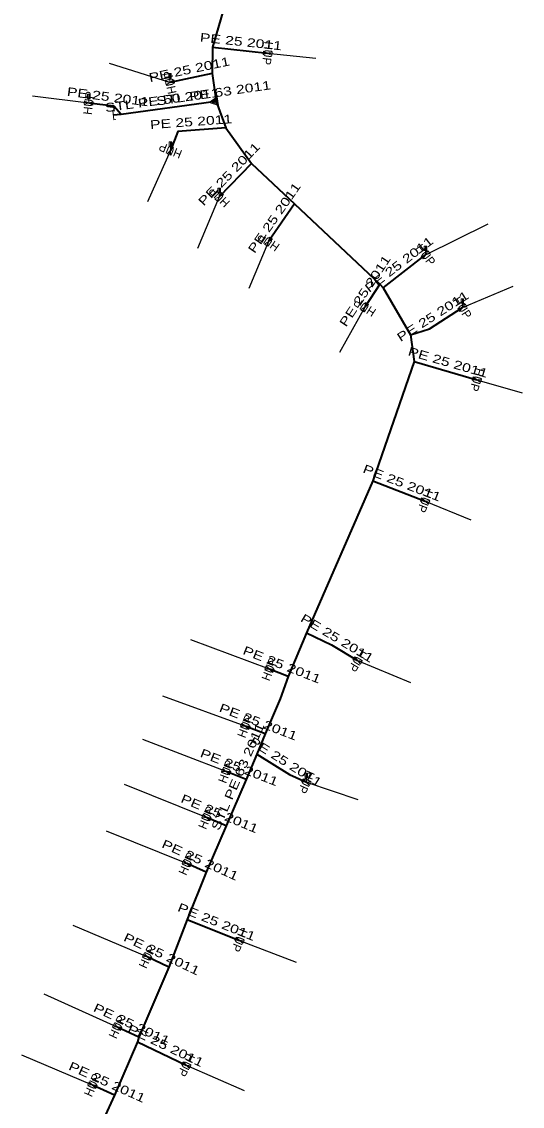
# Model space of a CAD drawing. Extents: x -737484 to -734496, y -1033882 to -1030666.
# Drawn here: x -735609.6 to -735552.2, y -1032516.8 to -1032392.5 of the extents above; entities that cross this region are included whole.
import ezdxf
from ezdxf.enums import TextEntityAlignment as Align

# ---------------------------------------------------------------- set-up
doc = ezdxf.new("R2010")
doc.units = 0
doc.header["$LTSCALE"] = 0.4
for name, color, linetype, lineweight in [('1', 7, 'Continuous', 13), ('22', 7, 'Continuous', 25), ('5', 7, 'Continuous', 35), ('7', 7, 'Continuous', 35)]:
    doc.layers.add(name, color=color, linetype=linetype, lineweight=lineweight)
doc.layers.add('2', color=7, linetype='Continuous')

msp = doc.modelspace()

# ---------------------------------------------------------------- linework, layer by layer
at = {"layer": '1'}
for p, q in [((-735592.6, -1032399.45), (-735592.6, -1032398.95)), ((-735592.525, -1032398.875), (-735592.525, -1032398.525)), ((-735601.914, -1032401.817), (-735601.914, -1032401.317)), ((-735601.839, -1032401.242), (-735601.839, -1032400.892)), ((-735592.55, -1032407.25), (-735592.55, -1032406.75)), ((-735592.475, -1032406.675), (-735592.475, -1032406.325)), ((-735586.875, -1032411.995), (-735586.875, -1032411.645)), ((-735586.95, -1032412.57), (-735586.95, -1032412.07)), ((-735563.29, -1032419.23), (-735563.29, -1032418.73)), ((-735563.215, -1032418.655), (-735563.215, -1032418.305)), ((-735558.995, -1032424.705), (-735558.995, -1032424.355)), ((-735559.07, -1032425.28), (-735559.07, -1032424.78)), ((-735576.885, -1032479.095), (-735576.885, -1032478.745)), ((-735576.96, -1032479.67), (-735576.96, -1032479.17))]:
    msp.add_line(p, q, dxfattribs=at)
for points in [[(-735580.881, -1032395.963), (-735580.923, -1032396.361), (-735581.876, -1032395.858), (-735581.918, -1032396.256)], [(-735593.047, -1032399.749), (-735593.13, -1032399.358), (-735592.069, -1032399.541), (-735592.152, -1032399.15)], [(-735592.6, -1032398.45), (-735592.75, -1032398.45), (-735592.75, -1032398.95), (-735592.6, -1032398.95)], [(-735592.6, -1032398.45), (-735592.45, -1032398.45), (-735592.45, -1032398.95), (-735592.6, -1032398.95)], [(-735592.563, -1032398.488), (-735592.488, -1032398.488), (-735592.488, -1032398.913), (-735592.563, -1032398.913)], [(-735602.434, -1032401.954), (-735602.385, -1032401.557), (-735601.442, -1032402.076), (-735601.393, -1032401.679)], [(-735601.914, -1032400.817), (-735602.064, -1032400.817), (-735602.064, -1032401.317), (-735601.914, -1032401.317)], [(-735601.914, -1032400.817), (-735601.764, -1032400.817), (-735601.764, -1032401.317), (-735601.914, -1032401.317)], [(-735601.877, -1032400.855), (-735601.802, -1032400.855), (-735601.802, -1032401.28), (-735601.877, -1032401.28)], [(-735587.052, -1032402.115), (-735587.191, -1032401.125), (-735588.112, -1032401.759)], [(-735587.267, -1032401.299), (-735587.89, -1032401.728), (-735587.173, -1032401.969)], [(-735587.669, -1032401.697), (-735587.295, -1032401.822), (-735587.344, -1032401.472)], [(-735592.551, -1032407.788), (-735592.922, -1032407.638), (-735592.177, -1032406.861), (-735592.548, -1032406.711)], [(-735592.55, -1032406.25), (-735592.7, -1032406.25), (-735592.7, -1032406.75), (-735592.55, -1032406.75)], [(-735592.55, -1032406.25), (-735592.4, -1032406.25), (-735592.4, -1032406.75), (-735592.55, -1032406.75)], [(-735592.513, -1032406.288), (-735592.438, -1032406.288), (-735592.438, -1032406.713), (-735592.513, -1032406.713)], [(-735586.95, -1032411.57), (-735587.1, -1032411.57), (-735587.1, -1032412.07), (-735586.95, -1032412.07)], [(-735586.95, -1032411.57), (-735586.8, -1032411.57), (-735586.8, -1032412.07), (-735586.95, -1032412.07)], [(-735586.913, -1032411.608), (-735586.838, -1032411.608), (-735586.838, -1032412.033), (-735586.913, -1032412.033)], [(-735587.153, -1032413.068), (-735587.441, -1032412.79), (-735586.458, -1032412.349), (-735586.746, -1032412.071)], [(-735581.432, -1032418.234), (-735581.76, -1032418.004), (-735580.859, -1032417.415), (-735581.187, -1032417.185)], [(-735563.019, -1032418.764), (-735562.772, -1032419.079), (-735563.807, -1032419.38), (-735563.56, -1032419.695)], [(-735563.29, -1032418.23), (-735563.44, -1032418.23), (-735563.44, -1032418.73), (-735563.29, -1032418.73)], [(-735563.29, -1032418.23), (-735563.14, -1032418.23), (-735563.14, -1032418.73), (-735563.29, -1032418.73)], [(-735563.253, -1032418.268), (-735563.178, -1032418.268), (-735563.178, -1032418.693), (-735563.253, -1032418.693)], [(-735559.07, -1032424.28), (-735559.22, -1032424.28), (-735559.22, -1032424.78), (-735559.07, -1032424.78)], [(-735559.07, -1032424.28), (-735558.92, -1032424.28), (-735558.92, -1032424.78), (-735559.07, -1032424.78)], [(-735559.033, -1032424.318), (-735558.958, -1032424.318), (-735558.958, -1032424.743), (-735559.033, -1032424.743)], [(-735570.374, -1032425.758), (-735570.71, -1032425.54), (-735569.829, -1032424.919), (-735570.165, -1032424.701)], [(-735558.759, -1032424.839), (-735558.541, -1032425.175), (-735559.598, -1032425.384), (-735559.38, -1032425.72)], [(-735556.864, -1032433.485), (-735556.974, -1032433.87), (-735557.825, -1032433.209), (-735557.935, -1032433.594)], [(-735562.801, -1032447.442), (-735562.944, -1032447.815), (-735563.735, -1032447.084), (-735563.878, -1032447.457)], [(-735570.548, -1032465.826), (-735570.754, -1032466.168), (-735571.405, -1032465.311), (-735571.611, -1032465.653)], [(-735581.728, -1032466.737), (-735581.585, -1032466.364), (-735580.794, -1032467.095), (-735580.651, -1032466.722)], [(-735584.498, -1032473.277), (-735584.355, -1032472.904), (-735583.564, -1032473.635), (-735583.421, -1032473.262)], [(-735586.698, -1032478.477), (-735586.555, -1032478.104), (-735585.764, -1032478.835), (-735585.621, -1032478.462)], [(-735576.96, -1032478.67), (-735577.11, -1032478.67), (-735577.11, -1032479.17), (-735576.96, -1032479.17)], [(-735576.96, -1032478.67), (-735576.81, -1032478.67), (-735576.81, -1032479.17), (-735576.96, -1032479.17)], [(-735576.923, -1032478.708), (-735576.848, -1032478.708), (-735576.848, -1032479.133), (-735576.923, -1032479.133)], [(-735576.421, -1032479.69), (-735576.584, -1032480.056), (-735577.335, -1032479.283), (-735577.498, -1032479.649)], [(-735588.948, -1032483.738), (-735588.792, -1032483.37), (-735588.027, -1032484.129), (-735587.871, -1032483.761)], [(-735591.198, -1032488.999), (-735591.035, -1032488.633), (-735590.284, -1032489.406), (-735590.121, -1032489.04)], [(-735584.091, -1032497.821), (-735584.241, -1032498.192), (-735585.018, -1032497.447), (-735585.168, -1032497.818)], [(-735595.747, -1032499.679), (-735595.578, -1032499.317), (-735594.841, -1032500.102), (-735594.672, -1032499.74)], [(-735599.187, -1032507.729), (-735599.018, -1032507.367), (-735598.281, -1032508.152), (-735598.112, -1032507.79)], [(-735590.192, -1032512.169), (-735590.368, -1032512.528), (-735591.091, -1032511.731), (-735591.267, -1032512.09)], [(-735602.028, -1032514.399), (-735601.865, -1032514.033), (-735601.114, -1032514.806), (-735600.951, -1032514.44)]]:
    msp.add_lwpolyline(points, close=True, dxfattribs=at)
msp.add_lwpolyline([(-735598.803, -1032403.699), (-735599.051, -1032403.725), (-735599.156, -1032402.73), (-735598.907, -1032402.704)], dxfattribs=at)
at = {"layer": '22'}
for p, q in [((-735581.4, -1032396.11), (-735575.873, -1032396.683)), ((-735592.6, -1032399.45), (-735599.553, -1032397.279)), ((-735601.914, -1032401.817), (-735608.35, -1032401.049)), ((-735592.55, -1032407.25), (-735595.187, -1032413.154)), ((-735586.95, -1032412.57), (-735589.433, -1032418.512)), ((-735563.29, -1032419.23), (-735556.095, -1032415.667)), ((-735581.31, -1032417.71), (-735583.546, -1032423.076)), ((-735559.07, -1032425.28), (-735553.251, -1032422.811)), ((-735570.27, -1032425.23), (-735573.161, -1032430.418)), ((-735557.4, -1032433.54), (-735552.192, -1032435.048)), ((-735563.34, -1032447.45), (-735558.079, -1032449.6)), ((-735581.19, -1032466.73), (-735590.226, -1032463.359)), ((-735571.08, -1032465.74), (-735565.025, -1032468.253)), ((-735583.96, -1032473.27), (-735593.401, -1032469.841)), ((-735586.16, -1032478.47), (-735595.716, -1032474.802)), ((-735588.41, -1032483.75), (-735597.833, -1032479.961)), ((-735576.96, -1032479.67), (-735571.044, -1032481.681)), ((-735590.66, -1032489.02), (-735599.884, -1032485.319)), ((-735595.21, -1032499.71), (-735603.72, -1032496.101)), ((-735584.63, -1032497.82), (-735578.122, -1032500.334)), ((-735598.65, -1032507.76), (-735607.027, -1032503.972)), ((-735601.49, -1032514.42), (-735609.607, -1032510.984)), ((-735590.73, -1032512.13), (-735584.075, -1032515.019))]:
    msp.add_line(p, q, dxfattribs=at)
at = {"layer": '5'}
msp.add_line((-735587.309, -1032401.646), (-735587.617, -1032401.69), dxfattribs=at)
for points in [[(-735566.96, -1032336.58), (-735575.32, -1032360.14), (-735577.82, -1032366.95), (-735579.54, -1032371.61), (-735580.01, -1032372.96), (-735582.5, -1032379.69), (-735583.64, -1032382.84), (-735584.28, -1032384.53), (-735585.22, -1032387.68), (-735586.09, -1032389.77), (-735587.74, -1032395.43), (-735587.77, -1032398.44), (-735587.309, -1032401.646)], [(-735587.309, -1032401.646), (-735586.19, -1032404.68), (-735583.25, -1032408.75), (-735578.31, -1032413.37), (-735568.53, -1032422.58), (-735568.16, -1032422.99), (-735565.02, -1032428.41), (-735564.58, -1032431.47), (-735569.35, -1032445.15), (-735576.93, -1032462.56), (-735579.06, -1032467.56), (-735579.97, -1032470.12), (-735581.69, -1032474.14), (-735582.62, -1032476.47), (-735583.87, -1032479.36), (-735586.17, -1032484.68), (-735588.44, -1032490.02), (-735590.61, -1032495.44), (-735592.74, -1032500.88), (-735596.17, -1032508.91), (-735596.32, -1032509.46), (-735598.95, -1032515.56), (-735601.91, -1032522.01)], [(-735587.617, -1032401.69), (-735598.186, -1032403.125), (-735599.104, -1032403.228)]]:
    msp.add_lwpolyline(points, dxfattribs=at)
at = {"layer": '7'}
for p, q in [((-735587.74, -1032395.43), (-735581.4, -1032396.11)), ((-735587.77, -1032398.44), (-735592.6, -1032399.45)), ((-735583.25, -1032408.75), (-735586.95, -1032412.57)), ((-735578.31, -1032413.37), (-735581.31, -1032417.71)), ((-735568.16, -1032422.99), (-735563.29, -1032419.23)), ((-735568.53, -1032422.58), (-735570.27, -1032425.23)), ((-735564.58, -1032431.47), (-735557.4, -1032433.54)), ((-735569.35, -1032445.15), (-735563.34, -1032447.45)), ((-735579.06, -1032467.56), (-735581.19, -1032466.73)), ((-735581.69, -1032474.14), (-735583.96, -1032473.27)), ((-735583.87, -1032479.36), (-735586.16, -1032478.47)), ((-735586.17, -1032484.68), (-735588.41, -1032483.75)), ((-735588.44, -1032490.02), (-735590.66, -1032489.02)), ((-735590.61, -1032495.44), (-735584.63, -1032497.82)), ((-735592.74, -1032500.88), (-735595.21, -1032499.71)), ((-735596.17, -1032508.91), (-735598.65, -1032507.76)), ((-735596.32, -1032509.46), (-735590.73, -1032512.13)), ((-735598.95, -1032515.56), (-735601.49, -1032514.42))]:
    msp.add_line(p, q, dxfattribs=at)
for points in [[(-735598.186, -1032403.125), (-735599.045, -1032402.188), (-735601.914, -1032401.817)], [(-735586.19, -1032404.68), (-735591.69, -1032405.08), (-735592.55, -1032407.25)], [(-735565.02, -1032428.41), (-735562.84, -1032427.7), (-735559.07, -1032425.28)], [(-735576.93, -1032462.56), (-735574.09, -1032463.94), (-735571.08, -1032465.74)], [(-735582.62, -1032476.47), (-735578.91, -1032478.79), (-735576.96, -1032479.67)]]:
    msp.add_lwpolyline(points, dxfattribs=at)

# ---------------------------------------------------------------- texts
at = {"layer": '2', "width": 0.95}
for rotation, p in [(264, (-735581.8967, -1032396.0572)), (102, (-735592.1108, -1032399.3455)), (83, (-735601.4173, -1032401.8774)), (158, (-735592.3622, -1032406.786)), (136, (-735586.6022, -1032412.2096)), (145, (-735581.0227, -1032417.3001)), (308, (-735563.683, -1032419.5377)), (303, (-735559.4881, -1032425.5522)), (147, (-735569.9972, -1032424.8101)), (254, (-735557.8798, -1032433.4017)), (249, (-735563.8063, -1032447.2703)), (239, (-735571.5082, -1032465.482)), (69, (-735580.7227, -1032466.9087)), (69, (-735583.4927, -1032473.4487)), (69, (-735585.6927, -1032478.6487)), (246, (-735577.4167, -1032479.4661)), (67, (-735587.9497, -1032483.9449)), (66, (-735590.2023, -1032489.2229)), (248, (-735585.093, -1032497.6322)), (65, (-735594.7564, -1032499.9208)), (65, (-735598.1964, -1032507.9708)), (244, (-735591.1785, -1032511.9103)), (66, (-735601.0323, -1032514.6229))]:
    msp.add_text('HUP', height=1, rotation=rotation, dxfattribs=at).set_placement(p, align=Align.CENTER)
at = {"layer": '5', "width": 1.35}
for s, rotation, p in [('STL PE 63 2011', 8.13, (-735587.5327, -1032401.1724)), ('STL PE 50 2011', 7.732, (-735593.4253, -1032401.9735)), ('STL PE 63 2011', 66.62, (-735584.3621, -1032479.2389))]:
    msp.add_text(s, height=1, rotation=rotation, dxfattribs=at).set_placement(p, align=Align.CENTER)
at = {"layer": '7', "width": 1.35}
for rotation, p in [(353.878, (-735584.5163, -1032395.272)), (11.811, (-735590.2863, -1032398.4546)), (352.632, (-735599.7846, -1032401.5878)), (4.16, (-735590.1403, -1032404.4659)), (45.914, (-735585.4588, -1032410.3114)), (55.346, (-735580.2212, -1032415.2553)), (37.671, (-735566.0301, -1032420.7139)), (56.711, (-735569.8176, -1032423.6299)), (32.697, (-735562.1891, -1032426.6883)), (343.918, (-735560.851, -1032432.0246)), (339.058, (-735566.1662, -1032445.8327)), (329.12, (-735573.6831, -1032463.6007)), (338.711, (-735579.9425, -1032466.6784)), (339.03, (-735582.6454, -1032473.2377)), (327.981, (-735579.5921, -1032477.7727)), (338.762, (-735584.8331, -1032478.4484)), (337.453, (-735587.0982, -1032483.7524)), (335.751, (-735589.3439, -1032489.064)), (338.298, (-735587.4349, -1032496.165)), (334.654, (-735593.7605, -1032499.8431)), (335.122, (-735597.1993, -1032507.8811)), (334.469, (-735593.309, -1032510.3438)), (335.829, (-735600.0152, -1032514.5332))]:
    msp.add_text('PE 25 2011', height=1, rotation=rotation, dxfattribs=at).set_placement(p, align=Align.CENTER)

doc.saveas('drawing.dxf')
